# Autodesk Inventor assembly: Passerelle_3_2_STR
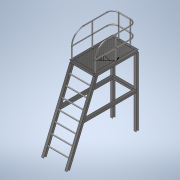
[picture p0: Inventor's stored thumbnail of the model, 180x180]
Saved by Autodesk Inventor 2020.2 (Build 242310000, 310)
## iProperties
_SolveAssemblyDoc: Frame Generator Solve Assembly
_Version: 15.0.0
Created: 2018-07
Part Number: Passerelle_3_2_STR
Material: Générique
Document SubType Name: Construction soudée
Designer: Fabian Perrée
Weld Material: Aluminium 6061, soudé
Mass: 574659 g
Surface Area: 487463 cm^2
Volume: 7.20489e+06 cm^3
Density: 0.0797595 g/cm^3
Author: Fabian Perrée
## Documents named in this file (4)
- C:\Users\Fabian\Google Drive\04_CAO\01_Inventor\01_Fichiers_exercice_Inventor\01_Definitif\Frame Generator\Passerelle_3_2_STR.iam
- C:\Users\Fabian\Google Drive\04_CAO\01_Inventor\01_Fichiers_exercice_Inventor\01_Definitif\Frame Generator\Passerelle_2_3_Sque_STR.ipt
- C:\Users\Fabian\Google Drive\04_CAO\01_Inventor\01_Fichiers_exercice_Inventor\01_Definitif\Frame Generator\Frame\Frame0001.iam
- C:\Users\Fabian\Google Drive\04_CAO\01_Inventor\01_Fichiers_exercice_Inventor\01_Definitif\Frame Generator\Plateforme_3_2_STR.ipt
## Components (3 placed, 3 different names)
1. Passerelle_2_3_Sque_STR:1 — Affleurement:1, Affleurement:2
2. Frame0001:1 [sub-assembly]
3. Plateforme_3_2_STR:1 — Affleurement:1, Affleurement:2
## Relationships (2: Flush 2)
- Affleurement:1 [Flush]: Passerelle_2_3_Sque_STR:1 ↔ Plateforme_3_2_STR:1
- Affleurement:2 [Flush]: Passerelle_2_3_Sque_STR:1 ↔ Plateforme_3_2_STR:1
